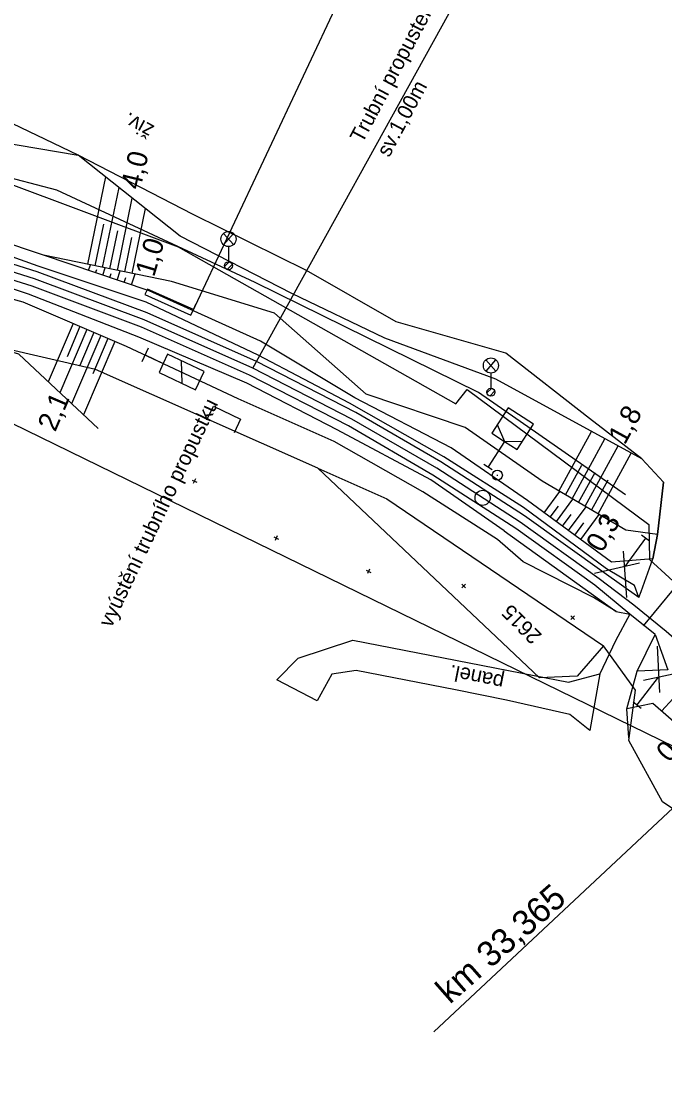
# Model space of a CAD drawing. Extents: x -805011 to -803920, y -1150790 to -1150234.
# Drawn here: x -804283.8 to -804219.9, y -1150562.3 to -1150457.1 of the extents above; entities that cross this region are included whole.
import ezdxf

# ---------------------------------------------------------------- set-up
doc = ezdxf.new("R2010")
doc.units = 0
for name, color, linetype in [('0381KM032-037P - Vrstva 1', 7, 'Continuous'), ('0381KM032-037P - Vrstva 17', 7, 'Continuous'), ('0381KM032-037P - Vrstva 19', 7, 'Continuous'), ('0381KM032-037P - Vrstva 25', 7, 'Continuous'), ('0381KM032-037P - Vrstva 4', 7, 'Continuous'), ('0381KM032-037P - Vrstva 43', 7, 'Continuous'), ('0381KM032-037P - Vrstva 48', 7, 'Continuous'), ('0381KM032-037P - Vrstva 49', 7, 'Continuous'), ('0381KM032-037P - Vrstva 51', 7, 'Continuous'), ('0381KM032-037P - Vrstva 55', 7, 'Continuous'), ('0381KM032-037P - Vrstva 57', 7, 'Continuous'), ('0381KM032-037P - Vrstva 6', 7, 'Continuous'), ('0381KM032-037P - Vrstva 7', 7, 'Continuous'), ('0381KM032-037P - Vrstva 9', 7, 'Continuous'), ('hran DP - hran DP', 7, 'Continuous'), ('vyt_sit - polygon', 7, 'Continuous')]:
    doc.layers.add(name, color=color, linetype=linetype)

msp = doc.modelspace()

# ---------------------------------------------------------------- linework, layer by layer
at = {"layer": '0381KM032-037P - Vrstva 1'}
for points in [[(-804222.98, -1150515.09), (-804226.42, -1150512.48), (-804234.26, -1150506.83), (-804242.54, -1150501.49), (-804250.96, -1150496.61), (-804260.8, -1150491.55), (-804271.59, -1150486.76), (-804282.48, -1150482.69), (-804291.53, -1150479.85), (-804302.34, -1150477.08), (-804311.51, -1150475.27), (-804320.67, -1150473.88), (-804330.92, -1150472.81), (-804341.55, -1150472.27), (-804345.19, -1150472.22)], [(-804170.82, -1150577.3), (-804176.26, -1150567.85), (-804182.37, -1150558.45), (-804188.8, -1150549.63), (-804195.8, -1150541.09), (-804203.2, -1150532.98), (-804210.73, -1150525.57), (-804219.76, -1150517.68), (-804222.98, -1150515.09)]]:
    msp.add_lwpolyline(points, dxfattribs=at)
at = {"layer": '0381KM032-037P - Vrstva 17'}
msp.add_lwpolyline([(-804223.8, -1150504.14), (-804238.39, -1150493.96), (-804260.56, -1150483.05), (-804280.24, -1150473.89), (-804302.47, -1150468.07)], dxfattribs=at)
at = {"layer": '0381KM032-037P - Vrstva 19'}
msp.add_line((-804260.8, -1150491.55), (-804226.07, -1150428.82), dxfattribs=at)
at = {"layer": '0381KM032-037P - Vrstva 25'}
for p, q in [((-804263.7, -1150478.18), (-804262.71, -1150479.29)), ((-804263.69, -1150479.31), (-804262.71, -1150478.19)), ((-804263.21, -1150479.49), (-804263.21, -1150480.99)), ((-804263.6, -1150481.47), (-804263.13, -1150481)), ((-804263.33, -1150481.77), (-804262.83, -1150481.27)), ((-804237.65, -1150490.73), (-804236.66, -1150491.84)), ((-804237.64, -1150491.86), (-804236.66, -1150490.74)), ((-804237.16, -1150492.04), (-804237.16, -1150493.54)), ((-804237.55, -1150494.02), (-804237.08, -1150493.55)), ((-804237.28, -1150494.32), (-804236.78, -1150493.82))]:
    msp.add_line(p, q, dxfattribs=at)
for centre, radius in [((-804263.21, -1150478.74), 0.749), ((-804263.21, -1150481.39), 0.4), ((-804263.21, -1150481.39), 0.4), ((-804237.16, -1150491.29), 0.749), ((-804237.16, -1150493.94), 0.4), ((-804237.16, -1150493.94), 0.4)]:
    msp.add_circle(centre, radius, dxfattribs=at)
at = {"layer": '0381KM032-037P - Vrstva 4'}
for p, q in [((-804186.06, -1150473.54), (-804222.06, -1150517.12)), ((-804221.4, -1150508.72), (-804222.2, -1150508.12)), ((-804221.8, -1150508.42), (-804223.88, -1150511.23)), ((-804223.68, -1150514.31), (-804224, -1150509.71)), ((-804222.4, -1150510.9), (-804226.89, -1150511.93)), ((-804219.76, -1150517.68), (-804222.98, -1150515.09)), ((-804220.66, -1150519.13), (-804220.42, -1150523.73)), ((-804222, -1150522.51), (-804217.49, -1150521.57)), ((-804222.65, -1150524.98), (-804220.51, -1150522.21)), ((-804223.05, -1150524.67), (-804222.25, -1150525.29))]:
    msp.add_line(p, q, dxfattribs=at)
for points in [[(-804225.7, -1150511.47), (-804233.93, -1150505.38), (-804241.84, -1150500.35), (-804251.18, -1150495.03), (-804260.27, -1150490.25), (-804271.39, -1150485.02), (-804282.1, -1150481.42), (-804291.28, -1150478.15), (-804302, -1150475.62), (-804311.22, -1150473.82), (-804320.47, -1150472.35), (-804331.17, -1150471.28), (-804341.36, -1150470.84), (-804345.11, -1150470.79), (-804355.15, -1150471.09), (-804364.49, -1150471.64), (-804373.72, -1150472.46), (-804382.56, -1150473.46), (-804390.64, -1150474.3), (-804394.58, -1150474.82), (-804430.68, -1150479.4), (-804471.16, -1150484.87), (-804515.79, -1150490.21)], [(-804222.47, -1150514.31), (-804225.93, -1150511.88), (-804233.81, -1150506.22), (-804242.12, -1150500.85), (-804250.57, -1150495.96), (-804260.44, -1150490.89), (-804271.28, -1150486.07), (-804282.21, -1150481.99), (-804291.28, -1150479.14), (-804302.11, -1150476.36), (-804311.33, -1150474.54), (-804320.55, -1150473.14), (-804330.83, -1150472.06), (-804341.5, -1150471.52), (-804345.16, -1150471.47), (-804355.1, -1150471.64), (-804364.39, -1150472.17), (-804373.73, -1150473.02), (-804382.33, -1150473.97), (-804390.45, -1150474.97), (-804394.45, -1150475.48), (-804430.79, -1150480.07), (-804470.48, -1150485.06), (-804515.61, -1150490.8)], [(-804223.37, -1150515.97), (-804226.85, -1150513.1), (-804234.67, -1150507.48), (-804242.93, -1150502.16), (-804251.31, -1150497.29), (-804261.13, -1150492.25), (-804271.85, -1150487.49), (-804282.71, -1150483.42), (-804291.73, -1150480.59), (-804302.46, -1150477.85), (-804311.66, -1150476.01), (-804320.71, -1150474.65), (-804330.94, -1150473.58), (-804341.55, -1150473.05), (-804345.16, -1150472.99), (-804355.02, -1150473.16), (-804364.28, -1150473.69), (-804373.57, -1150474.51), (-804382.12, -1150475.46), (-804390.26, -1150476.46), (-804394.25, -1150476.96), (-804430.61, -1150481.56), (-804470.33, -1150486.56), (-804515.43, -1150492.3)], [(-804235.83, -1150507.71), (-804243.11, -1150502.63), (-804252.43, -1150497.68), (-804261.4, -1150493.06), (-804272.11, -1150488.47), (-804283.06, -1150484.22), (-804291.82, -1150481.32), (-804302.89, -1150478.85), (-804311.92, -1150476.81), (-804320.92, -1150475.47), (-804331.06, -1150474.34), (-804341.56, -1150473.81), (-804345.45, -1150473.75), (-804355.04, -1150473.96), (-804364.32, -1150474.45), (-804373.64, -1150475.34), (-804382.1, -1150476.35), (-804390.24, -1150477.29), (-804394.24, -1150477.85), (-804430.45, -1150482.3), (-804470.19, -1150487.36), (-804515.37, -1150493.06)], [(-804235.83, -1150507.71), (-804224.74, -1150515.72), (-804223.37, -1150515.97)], [(-804222.47, -1150514.31), (-804222.91, -1150513.11), (-804225.7, -1150511.47)]]:
    msp.add_lwpolyline(points, dxfattribs=at)
at = {"layer": '0381KM032-037P - Vrstva 43'}
msp.add_lwpolyline([(-804265.36, -1150496.69), (-804264.71, -1150495.33), (-804262, -1150496.62), (-804262.65, -1150497.98)], dxfattribs=at)
at = {"layer": '0381KM032-037P - Vrstva 48'}
for p, q in [((-804277.17, -1150481.25), (-804275.39, -1150472.58)), ((-804275.7, -1150481.55), (-804274.07, -1150473.62)), ((-804274.23, -1150481.85), (-804272.76, -1150474.67)), ((-804272.76, -1150482.15), (-804271.44, -1150475.71)), ((-804276.44, -1150481.4), (-804275.58, -1150477.25)), ((-804274.97, -1150481.7), (-804274.19, -1150477.92)), ((-804273.5, -1150482), (-804272.8, -1150478.59)), ((-804277.11, -1150481.85), (-804276.92, -1150481.3)), ((-804276.4, -1150482.09), (-804276.29, -1150481.77)), ((-804275.69, -1150482.33), (-804275.44, -1150481.6)), ((-804274.27, -1150482.81), (-804273.96, -1150481.91)), ((-804274.98, -1150482.57), (-804274.84, -1150482.16)), ((-804273.56, -1150483.05), (-804273.39, -1150482.55)), ((-804272.85, -1150483.29), (-804272.48, -1150482.21)), ((-804278.64, -1150487.13), (-804281.11, -1150492.91)), ((-804277.26, -1150487.72), (-804279.94, -1150494)), ((-804277.95, -1150487.43), (-804279.23, -1150490.44)), ((-804276.57, -1150488.02), (-804277.96, -1150491.28)), ((-804275.88, -1150488.31), (-804278.78, -1150495.09)), ((-804274.5, -1150488.9), (-804277.61, -1150496.19)), ((-804275.19, -1150488.6), (-804276.69, -1150492.12)), ((-804230.4, -1150503.75), (-804227.17, -1150497.84)), ((-804229.1, -1150504.51), (-804225.85, -1150498.56)), ((-804227.81, -1150505.26), (-804224.53, -1150499.28)), ((-804226.51, -1150506.02), (-804223.22, -1150500)), ((-804229.75, -1150504.13), (-804228.13, -1150501.17)), ((-804228.45, -1150504.88), (-804226.82, -1150501.9)), ((-804227.16, -1150505.64), (-804225.52, -1150502.64)), ((-804231.86, -1150505.91), (-804230.32, -1150503.8)), ((-804230.65, -1150506.79), (-804229.01, -1150504.56)), ((-804231.26, -1150506.35), (-804230.46, -1150505.26)), ((-804230.05, -1150507.24), (-804229.2, -1150506.09)), ((-804229.44, -1150507.68), (-804227.71, -1150505.32)), ((-804228.23, -1150508.57), (-804226.41, -1150506.08)), ((-804228.84, -1150508.12), (-804227.95, -1150506.91)), ((-804220.22, -1150525.59), (-804217.9, -1150523.08))]:
    msp.add_line(p, q, dxfattribs=at)
at = {"layer": '0381KM032-037P - Vrstva 49'}
for p, q in [((-804266.82, -1150502.66), (-804266.36, -1150502.88)), ((-804266.48, -1150502.54), (-804266.7, -1150503)), ((-804258.36, -1150508.19), (-804258.58, -1150508.65)), ((-804220.62, -1150508.07), (-804221.1, -1150510.47)), ((-804258.7, -1150508.31), (-804258.24, -1150508.53)), ((-804249.54, -1150511.61), (-804249.08, -1150511.83)), ((-804249.2, -1150511.49), (-804249.42, -1150511.95)), ((-804239.68, -1150513.36), (-804240.04, -1150513)), ((-804239.68, -1150513), (-804240.04, -1150513.36)), ((-804224.74, -1150515.72), (-804226.97, -1150514.32)), ((-804228.85, -1150516.15), (-804229.21, -1150516.51)), ((-804229.21, -1150516.15), (-804228.85, -1150516.51)), ((-804220.84, -1150517.99), (-804219.6, -1150521.51)), ((-804219.6, -1150521.51), (-804222.65, -1150521.62)), ((-804221.09, -1150524.83), (-804223.68, -1150525.36))]:
    msp.add_line(p, q, dxfattribs=at)
for points in [[(-804320.34, -1150463.27), (-804278.12, -1150470.41)], [(-804221.1, -1150510.47), (-804225.19, -1150510.8), (-804233.52, -1150504.69), (-804241.09, -1150499.46), (-804250.66, -1150494.51), (-804260.04, -1150488.87), (-804271.07, -1150483.89), (-804281.58, -1150480.34), (-804290.68, -1150477.29), (-804301.47, -1150474.53), (-804310.76, -1150472.67), (-804320.3, -1150471.51), (-804330.99, -1150470.46), (-804340.83, -1150469.83), (-804345.1, -1150470.19), (-804354.95, -1150469.89)], [(-804222.18, -1150500.57), (-804236.67, -1150492.64), (-804247.69, -1150488.59), (-804256.93, -1150484.13), (-804267.99, -1150478.45), (-804278.12, -1150470.41)], [(-804226.97, -1150514.32), (-804233.94, -1150510.78), (-804236.52, -1150508.57), (-804243.93, -1150503.82), (-804252.72, -1150498.82), (-804262.25, -1150494.6), (-804273.33, -1150489.4), (-804283.59, -1150485.01), (-804292.89, -1150482.47), (-804303.02, -1150479.68), (-804312.2, -1150478.16), (-804321.12, -1150476.62), (-804331.14, -1150475.24), (-804341.8, -1150475.06), (-804345.41, -1150474.87), (-804355.14, -1150475.34), (-804364.22, -1150475.73), (-804373.58, -1150476.33), (-804382.14, -1150477.38), (-804390.01, -1150478.23), (-804394.36, -1150478.78), (-804430.35, -1150482.91), (-804470.16, -1150488.05), (-804515.21, -1150493.93)], [(-804276.15, -1150497.56), (-804284.03, -1150490.16), (-804299.15, -1150485.83), (-804306.89, -1150483.98), (-804317.28, -1150482.7), (-804327.05, -1150481.84), (-804338.6, -1150481.41), (-804350.55, -1150480.59), (-804360.54, -1150481.11), (-804374.96, -1150483.29), (-804385.39, -1150485.41), (-804391.71, -1150485.5), (-804430.73, -1150489.32), (-804470.3, -1150492.85), (-804514.17, -1150497.56)], [(-804220.62, -1150508.07), (-804223.76, -1150507.62), (-804232.08, -1150502.77), (-804239.7, -1150497.43), (-804249.53, -1150494.12), (-804258.64, -1150486.1), (-804268.88, -1150482.95), (-804281.58, -1150480.34)], [(-804222.18, -1150500.57), (-804220.01, -1150502.88), (-804220.62, -1150508.07)], [(-804220.84, -1150517.99), (-804223.37, -1150515.97), (-804224.79, -1150518.63), (-804226.34, -1150521.9), (-804227.33, -1150527.53)], [(-804223.68, -1150525.36), (-804222.65, -1150521.62), (-804220.84, -1150517.99)], [(-804191.88, -1150555.68), (-804193.53, -1150552.03), (-804203.25, -1150540.38), (-804221.09, -1150524.83)]]:
    msp.add_lwpolyline(points, dxfattribs=at)
at = {"layer": '0381KM032-037P - Vrstva 51'}
for points in [[(-804222.47, -1150514.31), (-804222.23, -1150513.73), (-804221.1, -1150510.47), (-804220.62, -1150508.07), (-804220.01, -1150502.88), (-804222.18, -1150500.57), (-804227.38, -1150496.55), (-804235.69, -1150490.06), (-804246.55, -1150486.97), (-804255.48, -1150481.87), (-804266.7, -1150476.32), (-804278.12, -1150470.41), (-804293.62, -1150463)], [(-804223.37, -1150515.97), (-804224.79, -1150518.63), (-804226.34, -1150521.9), (-804227.33, -1150527.53)], [(-804227.33, -1150527.53), (-804229.32, -1150525.92), (-804235.62, -1150524.51), (-804240.66, -1150523.49), (-804250.54, -1150521.55), (-804252.94, -1150521.92), (-804254.39, -1150524.56), (-804258.4, -1150522.49), (-804256.28, -1150520.34), (-804250.86, -1150518.54), (-804232.85, -1150522.07), (-804229.47, -1150522.71), (-804226.34, -1150521.9)], [(-804223.45, -1150528.25), (-804223.68, -1150525.36), (-804222.65, -1150521.62), (-804220.84, -1150517.99)]]:
    msp.add_lwpolyline(points, dxfattribs=at)
at = {"layer": '0381KM032-037P - Vrstva 55'}
msp.add_lwpolyline([(-804254.35, -1150501.48), (-804247.48, -1150504.53), (-804225.97, -1150519.11), (-804228.6, -1150522.11), (-804232.32, -1150522.3)], close=True, dxfattribs=at)
at = {"layer": '0381KM032-037P - Vrstva 6'}
msp.add_line((-804212.64, -1150529.17), (-804242.83, -1150557.41), dxfattribs=at)
at = {"layer": '0381KM032-037P - Vrstva 7'}
for p, q in [((-804271.17, -1150489.56), (-804271.81, -1150490.92)), ((-804267.9, -1150490.82), (-804267.84, -1150493.06)), ((-804235.81, -1150498.82), (-804237.44, -1150501.34)), ((-804237.86, -1150501.07), (-804237.02, -1150501.61)), ((-804236.57, -1150502.17), (-804236.47, -1150502.17))]:
    msp.add_line(p, q, dxfattribs=at)
for points in [[(-804271.49, -1150490.24), (-804269.68, -1150491.09), (-804270.1, -1150491.99), (-804266.48, -1150493.69), (-804265.63, -1150491.88), (-804269.25, -1150490.18), (-804269.68, -1150491.09)], [(-804235.81, -1150498.82), (-804234.55, -1150499.63), (-804232.93, -1150497.11), (-804235.45, -1150495.48), (-804237.07, -1150498.01), (-804235.81, -1150498.82)], [(-804236.53, -1150497.16), (-804235.81, -1150498.82), (-804234.01, -1150498.79)]]:
    msp.add_lwpolyline(points, dxfattribs=at)
for centre, radius in [((-804236.52, -1150502.17), 0.5), ((-804237.98, -1150504.43), 0.75)]:
    msp.add_circle(centre, radius, dxfattribs=at)
at = {"layer": '0381KM032-037P - Vrstva 9'}
for p, q in [((-804237.76, -1150424.25), (-804266.81, -1150486.01)), ((-804271.26, -1150483.71), (-804271.5, -1150484.26)), ((-804266.69, -1150485.74), (-804271.26, -1150483.71)), ((-804271.5, -1150484.26), (-804266.93, -1150486.28)), ((-804266.93, -1150486.28), (-804266.69, -1150485.74)), ((-804266.69, -1150485.74), (-804266.45, -1150485.19))]:
    msp.add_line(p, q, dxfattribs=at)
at = {"layer": 'hran DP - hran DP'}
for p, q in [((-804301.77, -1150466.98), (-804268.19, -1150479.5)), ((-804268.19, -1150479.5), (-804240.65, -1150495.11)), ((-804276.4, -1150491.69), (-804317.89, -1150482.17)), ((-804254.35, -1150501.48), (-804276.4, -1150491.69)), ((-804240.65, -1150495.11), (-804239.52, -1150493.68)), ((-804239.52, -1150493.68), (-804221.47, -1150507.06)), ((-804232.32, -1150522.3), (-804254.35, -1150501.48)), ((-804221.47, -1150507.06), (-804221.41, -1150510.55)), ((-804221.41, -1150510.55), (-804216.71, -1150514.88)), ((-804225.97, -1150519.11), (-804228.6, -1150522.11)), ((-804222.81, -1150523.51), (-804225.97, -1150519.11)), ((-804228.6, -1150522.11), (-804232.32, -1150522.3)), ((-804223.47, -1150528.51), (-804222.81, -1150523.51)), ((-804220.13, -1150534.61), (-804223.47, -1150528.51)), ((-804207.3, -1150543.14), (-804220.13, -1150534.61))]:
    msp.add_line(p, q, dxfattribs=at)
at = {"layer": 'vyt_sit - polygon'}
msp.add_line((-804328.27, -1150475.77), (-804184.81, -1150545.81), dxfattribs=at)

# ---------------------------------------------------------------- texts
at = {"layer": '0381KM032-037P - Vrstva 19'}
for s, p in [('Trubní propustek zasypán', (-804249.91, -1150469.3)), ('sv.1,00m', (-804247.26, -1150470.71))]:
    msp.add_text(s, height=1.5, rotation=61.9777, dxfattribs=at).set_placement(p)
at = {"layer": '0381KM032-037P - Vrstva 43'}
msp.add_text('vyústění trubního propustku', height=1.5, rotation=64.5558, dxfattribs=at).set_placement((-804274.83, -1150517.39))
at = {"layer": '0381KM032-037P - Vrstva 48'}
for s, rotation, p in [('4,0', 76.5616, (-804271.98, -1150473.92)), ('1,0', 73.3867, (-804270.6, -1150482.58)), ('2,1', 66.8351, (-804280.4, -1150497.95)), ('1,8', 61.3093, (-804223.87, -1150499.25)), ('0,3', 59.7607, (-804226.12, -1150509.96)), ('0,6', 47.212, (-804219.48, -1150530.78))]:
    msp.add_text(s, height=2, rotation=rotation, dxfattribs=at).set_placement(p)
at = {"layer": '0381KM032-037P - Vrstva 51'}
for s, rotation, p in [('živ.', 151.1139, (-804270.48, -1150467.55)), ('panel.', 168.559, (-804235.76, -1150522.06))]:
    msp.add_text(s, height=1.5, rotation=rotation, dxfattribs=at).set_placement(p)
at = {"layer": '0381KM032-037P - Vrstva 57'}
msp.add_text('2615', height=1.5, rotation=135.0206, dxfattribs=at).set_placement((-804232.02, -1150518.03))
at = {"layer": '0381KM032-037P - Vrstva 6'}
msp.add_text('km 33,365', height=2.5, rotation=41.3444, dxfattribs=at).set_placement((-804241.24, -1150554.74))

doc.saveas('drawing.dxf')
